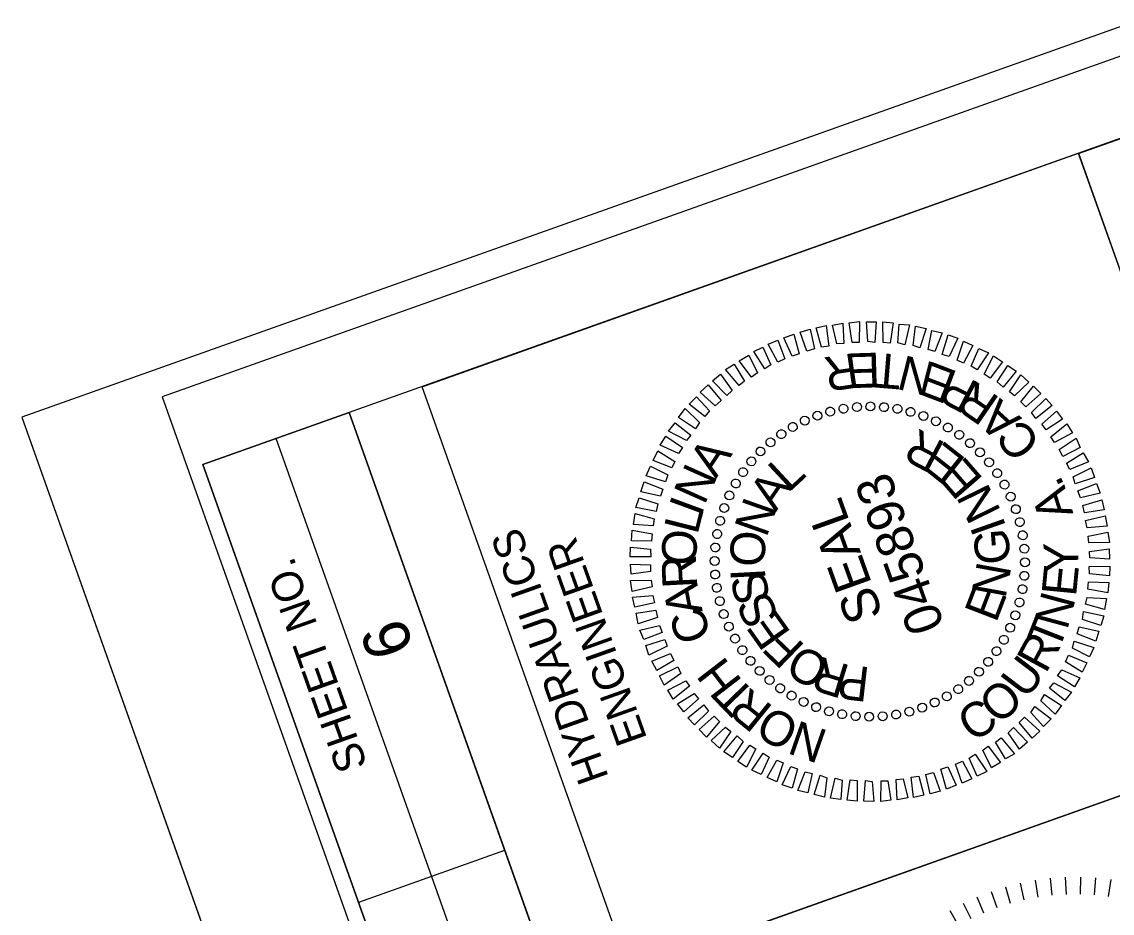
# Model space of a CAD drawing. Extents: x 1615843 to 1617444, y 901957 to 903921.
# Drawn here: x 1615843 to 1616019.1, y 903472.3 to 903616.2 of the extents above; entities that cross this region are included whole.
import ezdxf

# ---------------------------------------------------------------- set-up
doc = ezdxf.new("R2010")
doc.units = 0
for name, color, linetype in [('Default', 7, 'Continuous'), ('Exist Plan Preparation Drainage Flow Arrows', 7, 'Continuous'), ('Exist Plan Preparation Drainage Notes Label', 7, 'Continuous'), ('Exist Structure Minor Pipes CMP 15 Inch Text', 7, 'Continuous'), ('Exist Structure Minor Pipes CMP 24 Inch Text', 7, 'Continuous'), ('Prop Drainage Structure Catch Basin Grate 840 03E CELL', 7, 'Continuous'), ('Prop Plan Preparation Cover Label', 7, 'Continuous'), ('Scratch_Level_7', 7, 'Continuous')]:
    doc.layers.add(name, color=color, linetype=linetype)

msp = doc.modelspace()

# ---------------------------------------------------------------- linework, layer by layer
at = {"layer": 'Default'}
for p, q in [((1615971.54, 903552.71), (1615971.54, 903552.71)), ((1615973.65, 903553.36), (1615973.65, 903553.36)), ((1615975.73, 903553.79), (1615975.73, 903553.79)), ((1615977.96, 903554.06), (1615977.96, 903554.06)), ((1615980.11, 903554.14), (1615980.11, 903554.14)), ((1615982.27, 903554.06), (1615982.27, 903554.06)), ((1615984.44, 903553.78), (1615984.44, 903553.78)), ((1615986.59, 903553.28), (1615986.59, 903553.28)), ((1615988.69, 903552.6), (1615988.69, 903552.6)), ((1615967.6, 903550.81), (1615967.6, 903550.81)), ((1615969.52, 903551.82), (1615969.52, 903551.82)), ((1615990.69, 903551.77), (1615990.69, 903551.77)), ((1615965.68, 903549.65), (1615965.68, 903549.65)), ((1615992.65, 903550.73), (1615992.65, 903550.73)), ((1615994.42, 903549.5), (1615994.42, 903549.5)), ((1615963.97, 903548.34), (1615963.97, 903548.34)), ((1615996.21, 903548.23), (1615996.21, 903548.23)), ((1615962.38, 903546.87), (1615962.38, 903546.87)), ((1615997.82, 903546.69), (1615997.82, 903546.69)), ((1615960.88, 903545.27), (1615960.88, 903545.27)), ((1615999.3, 903545.09), (1615999.3, 903545.09)), ((1615959.55, 903543.51), (1615959.55, 903543.51)), ((1616000.61, 903543.38), (1616000.61, 903543.38)), ((1615958.32, 903541.74), (1615958.32, 903541.74)), ((1616001.76, 903541.51), (1616001.76, 903541.51)), ((1615957.29, 903539.73), (1615957.29, 903539.73)), ((1616002.73, 903539.53), (1616002.73, 903539.53)), ((1615956.45, 903537.78), (1615956.45, 903537.78)), ((1616003.62, 903537.51), (1616003.62, 903537.51)), ((1615955.79, 903535.63), (1615955.79, 903535.63)), ((1616004.25, 903535.45), (1616004.25, 903535.45)), ((1615955.32, 903533.55), (1615955.32, 903533.55)), ((1616004.7, 903533.32), (1616004.7, 903533.32)), ((1615955.03, 903531.37), (1615955.03, 903531.37)), ((1616005, 903531.15), (1616005, 903531.15)), ((1615954.91, 903529.2), (1615954.91, 903529.2)), ((1616005.1, 903528.95), (1616005.1, 903528.95)), ((1615955.01, 903527.01), (1615955.01, 903527.01)), ((1616004.97, 903526.78), (1616004.97, 903526.78)), ((1615955.31, 903524.83), (1615955.31, 903524.83)), ((1616004.69, 903524.61), (1616004.69, 903524.61)), ((1615955.75, 903522.71), (1615955.75, 903522.71)), ((1616004.19, 903522.46), (1616004.19, 903522.46)), ((1615956.36, 903520.58), (1615956.36, 903520.58)), ((1616003.56, 903520.38), (1616003.56, 903520.38)), ((1615957.24, 903518.56), (1615957.24, 903518.56)), ((1616002.68, 903518.36), (1616002.68, 903518.36)), ((1615958.25, 903516.64), (1615958.25, 903516.64)), ((1616001.69, 903516.41), (1616001.69, 903516.41)), ((1615959.4, 903514.77), (1615959.4, 903514.77)), ((1616000.46, 903514.64), (1616000.46, 903514.64)), ((1615960.72, 903513.01), (1615960.72, 903513.01)), ((1615999.13, 903512.89), (1615999.13, 903512.89)), ((1615962.18, 903511.47), (1615962.18, 903511.47)), ((1615997.63, 903511.29), (1615997.63, 903511.29)), ((1615963.78, 903509.97), (1615963.78, 903509.97)), ((1615965.54, 903508.63), (1615965.54, 903508.63)), ((1615994.28, 903508.49), (1615994.28, 903508.49)), ((1615996.03, 903509.81), (1615996.03, 903509.81)), ((1615967.32, 903507.36), (1615967.32, 903507.36)), ((1615992.41, 903507.34), (1615992.41, 903507.34)), ((1615969.32, 903506.38), (1615969.32, 903506.38)), ((1615971.29, 903505.49), (1615971.29, 903505.49)), ((1615988.46, 903505.45), (1615988.46, 903505.45)), ((1615990.48, 903506.33), (1615990.48, 903506.33)), ((1615973.42, 903504.88), (1615973.42, 903504.88)), ((1615975.57, 903504.37), (1615975.57, 903504.37)), ((1615977.74, 903504.09), (1615977.74, 903504.09)), ((1615979.91, 903503.97), (1615979.91, 903503.97)), ((1615982.06, 903504.05), (1615982.06, 903504.05)), ((1615984.23, 903504.35), (1615984.23, 903504.35)), ((1615986.36, 903504.8), (1615986.36, 903504.8))]:
    msp.add_line(p, q, dxfattribs=at)
for points in [[(1615969.79, 903563.07), (1615968.69, 903566.13), (1615970.32, 903566.61), (1615971, 903563.4)], [(1615972.16, 903563.71), (1615971.31, 903566.81), (1615972.93, 903567.18), (1615973.33, 903563.87)], [(1615974.63, 903564.23), (1615973.91, 903567.27), (1615975.61, 903567.56), (1615975.78, 903564.27)], [(1615977.11, 903564.43), (1615976.61, 903567.6), (1615978.28, 903567.83), (1615978.22, 903564.45)], [(1615979.65, 903564.6), (1615979.4, 903567.8), (1615981, 903567.79), (1615980.76, 903564.47)], [(1615982.09, 903564.47), (1615982.06, 903567.8), (1615983.73, 903567.6), (1615983.25, 903564.35)], [(1615984.51, 903564.38), (1615984.69, 903567.42), (1615986.39, 903567.28), (1615985.63, 903564.09)], [(1615986.94, 903563.98), (1615987.36, 903567.1), (1615989.04, 903566.7), (1615988.04, 903563.57)], [(1615965.11, 903561.29), (1615963.54, 903564.18), (1615965.11, 903564.85), (1615966.21, 903561.79)], [(1615967.43, 903562.23), (1615966.1, 903565.2), (1615967.7, 903565.78), (1615968.56, 903562.64)], [(1615989.36, 903563.3), (1615990, 903566.4), (1615991.62, 903566.03), (1615990.47, 903563.01)], [(1615991.66, 903562.53), (1615992.59, 903565.69), (1615994.17, 903565.14), (1615992.79, 903562.2)], [(1615963, 903560.21), (1615961.22, 903562.97), (1615962.7, 903563.72), (1615964, 903560.84)], [(1615994.07, 903561.59), (1615995.09, 903564.67), (1615996.62, 903563.95), (1615995.09, 903561.11)], [(1615996.32, 903560.65), (1615997.58, 903563.49), (1615999.11, 903562.77), (1615997.28, 903560.04)], [(1615960.88, 903558.87), (1615958.88, 903561.49), (1615960.41, 903562.42), (1615961.8, 903559.57)], [(1615998.43, 903559.34), (1615999.93, 903562.27), (1616001.38, 903561.35), (1615999.41, 903558.68)], [(1615958.87, 903557.51), (1615956.68, 903560.07), (1615958.07, 903560.94), (1615959.7, 903558.18)], [(1616000.52, 903558.12), (1616002.25, 903560.71), (1616003.58, 903559.8), (1616001.47, 903557.24)], [(1615956.86, 903555.88), (1615954.57, 903558.25), (1615955.87, 903559.35), (1615957.72, 903556.72)], [(1616002.49, 903556.49), (1616004.32, 903559.22), (1616005.64, 903558.05), (1616003.35, 903555.85)], [(1615955.01, 903554.21), (1615952.57, 903556.41), (1615953.84, 903557.61), (1615955.93, 903555.07)], [(1616004.34, 903554.87), (1616006.4, 903557.42), (1616007.59, 903556.2), (1616005.17, 903554.05)], [(1615953.34, 903552.49), (1615950.77, 903554.49), (1615951.99, 903555.67), (1615954.08, 903553.4)], [(1616006.07, 903553.16), (1616008.39, 903555.42), (1616009.38, 903554.29), (1616006.79, 903552.19)], [(1615951.82, 903550.51), (1615949.09, 903552.35), (1615950.12, 903553.78), (1615952.46, 903551.54)], [(1616007.72, 903551.25), (1616010.09, 903553.38), (1616011.1, 903552.04), (1616008.42, 903550.33)], [(1615950.33, 903548.6), (1615947.45, 903550.11), (1615948.5, 903551.5), (1615951.03, 903549.48)], [(1616009.19, 903549.23), (1616011.78, 903551.33), (1616012.68, 903549.84), (1616009.78, 903548.32)], [(1615949.07, 903546.5), (1615946.13, 903547.88), (1615947, 903549.31), (1615949.73, 903547.48)], [(1616010.51, 903547.15), (1616013.26, 903548.99), (1616013.95, 903547.49), (1616011.12, 903546.04)], [(1615947.98, 903544.19), (1615945, 903545.41), (1615945.72, 903546.94), (1615948.47, 903545.22)], [(1616011.72, 903544.98), (1616014.42, 903546.64), (1616015.26, 903545.19), (1616012.25, 903543.95)], [(1615946.99, 903541.93), (1615943.82, 903542.91), (1615944.55, 903544.45), (1615947.33, 903543.06)], [(1616012.78, 903542.76), (1616015.72, 903544.19), (1616016.23, 903542.62), (1616013.14, 903541.62)], [(1615946.18, 903539.61), (1615943, 903540.33), (1615943.53, 903541.96), (1615946.51, 903540.74)], [(1616013.55, 903540.49), (1616016.57, 903541.68), (1616017.18, 903540.14), (1616014, 903539.37)], [(1615945.47, 903537.13), (1615942.2, 903537.81), (1615942.7, 903539.38), (1615945.71, 903538.39)], [(1616014.34, 903538.12), (1616017.41, 903539.06), (1616017.78, 903537.44), (1616014.61, 903536.94)], [(1615944.97, 903534.83), (1615941.81, 903535.07), (1615942.08, 903536.81), (1615945.15, 903535.95)], [(1616014.78, 903535.72), (1616017.97, 903536.44), (1616018.3, 903534.81), (1616015.04, 903534.54)], [(1615944.7, 903532.34), (1615941.49, 903532.4), (1615941.6, 903534.15), (1615944.8, 903533.54)], [(1616015.22, 903533.17), (1616018.38, 903533.83), (1616018.67, 903532.13), (1616015.34, 903532.1)], [(1615944.58, 903529.85), (1615941.25, 903529.82), (1615941.32, 903531.39), (1615944.52, 903531.05)], [(1616015.46, 903530.71), (1616018.62, 903531.1), (1616018.67, 903529.47), (1616015.47, 903529.65)], [(1615944.54, 903527.45), (1615941.41, 903527.01), (1615941.29, 903528.67), (1615944.52, 903528.55)], [(1616015.38, 903528.29), (1616018.71, 903528.32), (1616018.69, 903526.77), (1616015.44, 903527.09)], [(1615944.79, 903524.98), (1615941.6, 903524.26), (1615941.33, 903526.03), (1615944.67, 903526.06)], [(1616015.26, 903525.8), (1616018.54, 903525.7), (1616018.4, 903524.01), (1616015.16, 903524.6)], [(1615945.18, 903522.41), (1615942.03, 903521.71), (1615941.66, 903523.33), (1615944.92, 903523.59)], [(1616015.05, 903523.28), (1616018.2, 903523.09), (1616017.88, 903521.32), (1616014.81, 903522.19)], [(1615945.66, 903520.04), (1615942.57, 903519.03), (1615942.23, 903520.72), (1615945.4, 903521.22)], [(1616014.49, 903521.01), (1616017.76, 903520.32), (1616017.26, 903518.76), (1616014.31, 903519.72)], [(1615946.43, 903517.6), (1615943.44, 903516.48), (1615942.83, 903518.01), (1615946.02, 903518.73)], [(1616013.78, 903518.52), (1616016.96, 903517.81), (1616016.48, 903516.2), (1616013.45, 903517.39)], [(1615947.22, 903515.39), (1615944.28, 903513.96), (1615943.77, 903515.53), (1615946.84, 903516.47)], [(1616012.97, 903516.21), (1616016.15, 903515.18), (1616015.41, 903513.69), (1616012.68, 903515.1)], [(1615948.3, 903513.12), (1615945.54, 903511.49), (1615944.75, 903512.96), (1615947.76, 903514.2)], [(1616012.02, 903513.96), (1616015.02, 903512.7), (1616014.24, 903511.2), (1616011.56, 903512.89)], [(1615949.45, 903510.98), (1615946.77, 903509.12), (1615946.02, 903510.6), (1615948.95, 903512.08)], [(1616010.95, 903511.61), (1616013.88, 903510.27), (1616013.01, 903508.84), (1616010.25, 903510.61)], [(1615950.82, 903508.93), (1615948.23, 903506.83), (1615947.32, 903508.31), (1615950.23, 903509.83)], [(1616009.69, 903509.51), (1616012.52, 903507.98), (1616011.46, 903506.64), (1616009, 903508.62)], [(1615952.29, 903506.91), (1615949.92, 903504.78), (1615948.93, 903506.07), (1615951.61, 903507.78)], [(1616008.15, 903507.58), (1616010.91, 903505.81), (1616009.87, 903504.42), (1616007.56, 903506.57)], [(1615953.9, 903504.93), (1615951.63, 903502.68), (1615950.57, 903503.85), (1615953.17, 903505.95)], [(1616006.62, 903505.64), (1616009.24, 903503.66), (1616008.03, 903502.43), (1616005.94, 903504.71)], [(1615955.68, 903503.24), (1615953.6, 903500.74), (1615952.42, 903501.96), (1615954.84, 903504.1)], [(1616004.95, 903503.93), (1616007.4, 903501.68), (1616006.16, 903500.54), (1616004.08, 903503.09)], [(1615957.54, 903501.62), (1615955.69, 903498.93), (1615954.35, 903500.15), (1615956.65, 903502.31)], [(1616003.15, 903502.27), (1616005.44, 903499.91), (1616004.15, 903498.75), (1616002.28, 903501.43)], [(1615959.49, 903500.03), (1615957.76, 903497.45), (1615956.38, 903498.33), (1615958.53, 903500.91)], [(1616001.15, 903500.6), (1616003.34, 903498.04), (1616001.89, 903497.2), (1616000.28, 903499.91)], [(1615961.57, 903498.82), (1615960.07, 903495.89), (1615958.63, 903496.8), (1615960.61, 903499.43)], [(1615963.71, 903497.46), (1615962.43, 903494.66), (1615960.89, 903495.38), (1615962.73, 903498.12)], [(1615996.99, 903497.99), (1615998.85, 903495.15), (1615997.31, 903494.44), (1615996.01, 903497.32)], [(1615999.08, 903499.27), (1616001.08, 903496.64), (1615999.6, 903495.74), (1615998.21, 903498.59)], [(1615965.94, 903496.56), (1615964.92, 903493.48), (1615963.39, 903494.21), (1615964.94, 903497)], [(1615994.91, 903496.82), (1615996.46, 903493.97), (1615994.85, 903493.29), (1615993.8, 903496.36)], [(1615968.3, 903495.6), (1615967.41, 903492.47), (1615965.83, 903493.02), (1615967.22, 903495.96)], [(1615970.65, 903494.85), (1615969.96, 903491.73), (1615968.34, 903492.11), (1615969.53, 903495.14)], [(1615973.02, 903494.16), (1615972.65, 903491.05), (1615970.96, 903491.46), (1615971.92, 903494.56)], [(1615987.85, 903494.44), (1615988.69, 903491.34), (1615987.03, 903490.96), (1615986.63, 903494.27)], [(1615990.24, 903495.03), (1615991.34, 903491.97), (1615989.69, 903491.54), (1615989.03, 903494.7)], [(1615992.57, 903495.92), (1615993.91, 903492.95), (1615992.32, 903492.33), (1615991.44, 903495.52)], [(1615975.5, 903493.78), (1615975.28, 903490.67), (1615973.62, 903490.87), (1615974.38, 903494.07)], [(1615977.92, 903493.69), (1615977.93, 903490.4), (1615976.28, 903490.55), (1615976.76, 903493.8)], [(1615980.36, 903493.56), (1615980.6, 903490.35), (1615979.01, 903490.36), (1615979.25, 903493.69)], [(1615982.87, 903493.66), (1615983.35, 903490.54), (1615981.73, 903490.33), (1615981.81, 903493.65)], [(1615985.36, 903493.97), (1615986.09, 903490.89), (1615984.39, 903490.6), (1615984.22, 903493.88)]]:
    msp.add_lwpolyline(points, close=True, dxfattribs=at)
for centre, major_axis in [((1615975.71, 903553.76), (-0.122, 0.709)), ((1615977.88, 903554.03), (-0.06, 0.717)), ((1615980.06, 903554.12), (0.003, 0.719)), ((1615982.25, 903554.01), (0.066, 0.716)), ((1615984.41, 903553.72), (0.128, 0.708)), ((1615969.46, 903551.82), (-0.301, 0.653)), ((1615971.49, 903552.64), (-0.243, 0.677)), ((1615973.57, 903553.29), (-0.183, 0.696)), ((1615986.54, 903553.24), (0.189, 0.694)), ((1615988.62, 903552.57), (0.249, 0.675)), ((1615990.64, 903551.72), (0.307, 0.651)), ((1615967.52, 903550.81), (-0.357, 0.624)), ((1615992.57, 903550.71), (0.362, 0.621)), ((1615963.93, 903548.32), (-0.46, 0.553)), ((1615965.67, 903549.65), (-0.41, 0.591)), ((1615994.41, 903549.53), (0.415, 0.587)), ((1615996.14, 903548.19), (0.465, 0.549)), ((1615962.31, 903546.85), (-0.506, 0.511)), ((1615997.75, 903546.7), (0.511, 0.506)), ((1615960.83, 903545.25), (-0.549, 0.465)), ((1615999.22, 903545.09), (0.553, 0.46)), ((1615959.49, 903543.52), (-0.587, 0.415)), ((1616000.54, 903543.35), (0.591, 0.41)), ((1615958.31, 903541.68), (-0.621, 0.362)), ((1616001.71, 903541.5), (0.624, 0.357)), ((1615957.29, 903539.75), (-0.651, 0.307)), ((1616002.71, 903539.55), (0.653, 0.301)), ((1615956.45, 903537.73), (-0.675, 0.249)), ((1616003.54, 903537.53), (0.677, 0.243)), ((1615955.78, 903535.65), (-0.694, 0.189)), ((1616004.18, 903535.44), (0.696, 0.183)), ((1615955.3, 903533.52), (-0.708, 0.128)), ((1616004.65, 903533.31), (0.709, 0.122)), ((1615955, 903531.35), (-0.716, 0.066)), ((1616004.92, 903531.14), (0.717, 0.06)), ((1615954.9, 903529.17), (-0.719, 0.003)), ((1616005.01, 903528.96), (0.719, -0.003)), ((1615954.99, 903526.99), (-0.717, -0.06)), ((1616004.9, 903526.77), (0.716, -0.066)), ((1615955.26, 903524.82), (-0.709, -0.122)), ((1616004.61, 903524.61), (0.708, -0.128)), ((1615955.73, 903522.68), (-0.696, -0.183)), ((1616004.13, 903522.47), (0.694, -0.189)), ((1615956.37, 903520.59), (-0.677, -0.243)), ((1616003.46, 903520.39), (0.675, -0.249)), ((1615957.2, 903518.57), (-0.653, -0.301)), ((1616002.62, 903518.38), (0.651, -0.307)), ((1615958.2, 903516.63), (-0.624, -0.357)), ((1615959.37, 903514.78), (-0.591, -0.41)), ((1616001.6, 903516.44), (0.621, -0.362)), ((1615960.69, 903513.04), (-0.553, -0.46)), ((1616000.42, 903514.6), (0.587, -0.415)), ((1615962.16, 903511.42), (-0.511, -0.506)), ((1615997.6, 903511.27), (0.506, -0.511)), ((1615999.08, 903512.88), (0.549, -0.465)), ((1615963.77, 903509.94), (-0.465, -0.549)), ((1615995.98, 903509.8), (0.46, -0.553)), ((1615965.5, 903508.6), (-0.415, -0.587)), ((1615994.24, 903508.48), (0.41, -0.591)), ((1615967.33, 903507.42), (-0.362, -0.621)), ((1615969.27, 903506.4), (-0.307, -0.651)), ((1615990.45, 903506.31), (0.301, -0.653)), ((1615992.39, 903507.31), (0.357, -0.624)), ((1615971.29, 903505.56), (-0.249, -0.675)), ((1615973.37, 903504.89), (-0.189, -0.694)), ((1615975.5, 903504.41), (-0.128, -0.708)), ((1615984.2, 903504.37), (0.122, -0.709)), ((1615986.34, 903504.83), (0.183, -0.696)), ((1615988.42, 903505.48), (0.243, -0.677)), ((1615977.66, 903504.11), (-0.066, -0.716)), ((1615979.85, 903504.01), (-0.003, -0.719)), ((1615982.03, 903504.09), (0.06, -0.717))]:
    msp.add_ellipse(centre, major_axis=major_axis, ratio=0.999708, dxfattribs=at)
at = {"layer": 'Exist Plan Preparation Drainage Flow Arrows'}
msp.add_lwpolyline([(1615865.68, 903555.66), (1616423.91, 901985.43), (1617418.05, 902338.86), (1616859.83, 903909.09)], close=True, dxfattribs=at)
at = {"layer": 'Exist Plan Preparation Drainage Notes Label'}
msp.add_lwpolyline([(1615843.02, 903552.38), (1616407.11, 901965.67), (1617443.56, 902334.13), (1616879.47, 903920.85)], close=True, dxfattribs=at)
at = {"layer": 'Exist Structure Minor Pipes CMP 15 Inch Text'}
for p, q in [((1616013.67, 903594.99), (1616035.81, 903602.86)), ((1616080.66, 903406.51), (1616013.66, 903594.99))]:
    msp.add_line(p, q, dxfattribs=at)
at = {"layer": 'Exist Structure Minor Pipes CMP 24 Inch Text'}
msp.add_line((1615843.02, 903552.38), (1616407.11, 901965.67), dxfattribs=at)
at = {"layer": 'Prop Drainage Structure Catch Basin Grate 840 03E CELL'}
for p, q in [((1616004.25, 903477.15), (1616004.85, 903474.46)), ((1616006.65, 903477.62), (1616007.09, 903474.89)), ((1616009.08, 903477.93), (1616009.36, 903475.18)), ((1616011.53, 903478.1), (1616011.64, 903475.33)), ((1616013.98, 903478.12), (1616013.91, 903475.35)), ((1616016.42, 903477.99), (1616016.2, 903475.23)), ((1616018.86, 903477.71), (1616018.46, 903474.98)), ((1615999.54, 903475.8), (1616000.46, 903473.2)), ((1616001.88, 903476.55), (1616002.64, 903473.9)), ((1615995.03, 903473.89), (1615996.26, 903471.42)), ((1615997.26, 903474.92), (1615998.33, 903472.37)), ((1615992.87, 903472.74), (1615994.25, 903470.34))]:
    msp.add_line(p, q, dxfattribs=at)
at = {"layer": 'Prop Plan Preparation Cover Label'}
for p, q in [((1615962.88, 903364.63), (1615895.87, 903553.13)), ((1615962.88, 903364.63), (1615895.87, 903553.13)), ((1615951.11, 903360.45), (1615884.09, 903548.94)), ((1615941.15, 903463.09), (1616047.1, 903500.76)), ((1615897.44, 903474.09), (1615921, 903482.46))]:
    msp.add_line(p, q, dxfattribs=at)
for points in [[(1615872.27, 903544.74), (1616374.72, 902131.39), (1617364.06, 902483.11), (1616861.61, 903896.45)], [(1615941.15, 903463.09), (1615907.65, 903557.31), (1616013.65, 903595), (1616047.15, 903500.78)], [(1615939.28, 903356.24), (1615872.27, 903544.74), (1615895.87, 903553.13), (1615962.88, 903364.63)], [(1615974.66, 903368.82), (1615941.15, 903463.09), (1616047.15, 903500.78), (1616080.66, 903406.51)]]:
    msp.add_lwpolyline(points, close=True, dxfattribs=at)

# ---------------------------------------------------------------- texts
at = {"layer": 'Default'}
for s, height, rotation, p in [('R', 5.6, 188.3523, (1615977.61, 903562.78)), ('E', 5.6, 181.704, (1615981.53, 903562.82)), ('T', 5.6, 175.3034, (1615985.27, 903562.44)), ('N', 5.6, 165.7581, (1615990.73, 903561.11)), ('E', 5.6, 159.1098, (1615994.36, 903559.65)), ('P', 5.6, 152.4615, (1615997.8, 903557.78)), ('R', 5.6, 145.5161, (1616001.14, 903555.42)), ('A', 5.6, 137.4812, (1616004.61, 903552.2)), ('C', 5.6, 128.8521, (1616007.79, 903548.25)), ('R', 5.6, 152.2089, (1615992.39, 903548.14)), ('A', 5.6, 56.2597, (1615955.1, 903542.36)), ('E', 5.6, 141.6047, (1615995.68, 903545.53)), ('E', 5.6, 131.0005, (1615998.43, 903542.36)), ('N', 5.6, 65.8049, (1615953.25, 903538.05)), ('L', 5.6, 42.9242, (1615966.87, 903540.14)), ('A', 5.6, 55.5921, (1615964.77, 903536.99)), ('045893', 5.994, 109.7553, (1615992.09, 903518.68)), ('.', 5.6, 115.5432, (1616011.45, 903541.33)), ('N', 5.6, 116.0847, (1616001.22, 903537.17)), ('A', 5.6, 107.5083, (1616012.85, 903536.82)), ('I', 5.6, 69.8038, (1615952.69, 903536.16)), ('N', 5.6, 70.5079, (1615963.26, 903532.81)), ('SEAL', 5.992, 109.7553, (1615982.16, 903520.45)), ('L', 5.6, 75.7835, (1615952.11, 903533.28)), ('I', 5.6, 109.4237, (1616002.02, 903534.65)), ('O', 5.6, 85.9974, (1615951.81, 903528.27)), ('O', 5.6, 86.4188, (1615962.88, 903528.08)), ('G', 5.6, 94.5078, (1616002.7, 903528.8)), ('Y', 5.6, 91.0919, (1616013.69, 903527.21)), ('R', 5.6, 92.9428, (1615952.12, 903524.87)), ('N', 5.6, 79.592, (1616001.86, 903522.96)), ('E', 5.6, 84.4436, (1616013.25, 903523.32)), ('I', 5.6, 93.0798, (1615963.12, 903526.1)), ('S', 5.6, 103.9419, (1615963.98, 903522.98)), ('A', 5.6, 100.9776, (1615952.98, 903521.01)), ('E', 5.6, 68.9878, (1616000.35, 903519.04)), ('S', 5.6, 114.8041, (1615965.43, 903520.07)), ('N', 5.6, 74.8983, (1616011.83, 903517.89)), ('C', 5.6, 109.6068, (1615954.5, 903517.05)), ('E', 5.6, 125.4082, (1615967.34, 903517.54)), ('T', 5.6, 68.4977, (1616010.38, 903514.41)), ('R', 5.6, 61.5523, (1616008.38, 903510.84)), ('F', 5.6, 135.9019, (1615969.66, 903515.43)), ('O', 5.6, 151.8127, (1615973.8, 903513.12)), ('U', 5.6, 52.6384, (1616005.21, 903506.67)), ('H', 5.6, 127.6822, (1615959.5, 903509.74)), ('R', 5.6, 162.8591, (1615976.98, 903512.23)), ('P', 5.6, 173.4633, (1615980.13, 903511.96)), ('T', 5.6, 134.0828, (1615961.79, 903507.57)), ('R', 5.6, 141.0282, (1615964.53, 903505.53)), ('O', 5.6, 42.4246, (1616000.83, 903502.55)), ('O', 5.6, 151.242, (1615968.95, 903503.16)), ('C', 5.6, 33.7954, (1615996.61, 903499.73)), ('N', 5.6, 160.7873, (1615973.41, 903501.69))]:
    msp.add_text(s, height=height, rotation=rotation, dxfattribs=at).set_placement(p)
at = {"layer": 'Prop Plan Preparation Cover Label'}
for s, p in [('HYDRAULICS', (1615937.83, 903494.23)), ('ENGINEER', (1615944.04, 903500.47)), ('SHEET NO.', (1615898.88, 903496.14))]:
    msp.add_text(s, height=5, rotation=109.5707, dxfattribs=at).set_placement(p)
at = {"layer": 'Scratch_Level_7'}
msp.add_text('6', height=7.5, rotation=109.5707, dxfattribs=at).set_placement((1615906.45, 903515.03))

doc.saveas('drawing.dxf')
